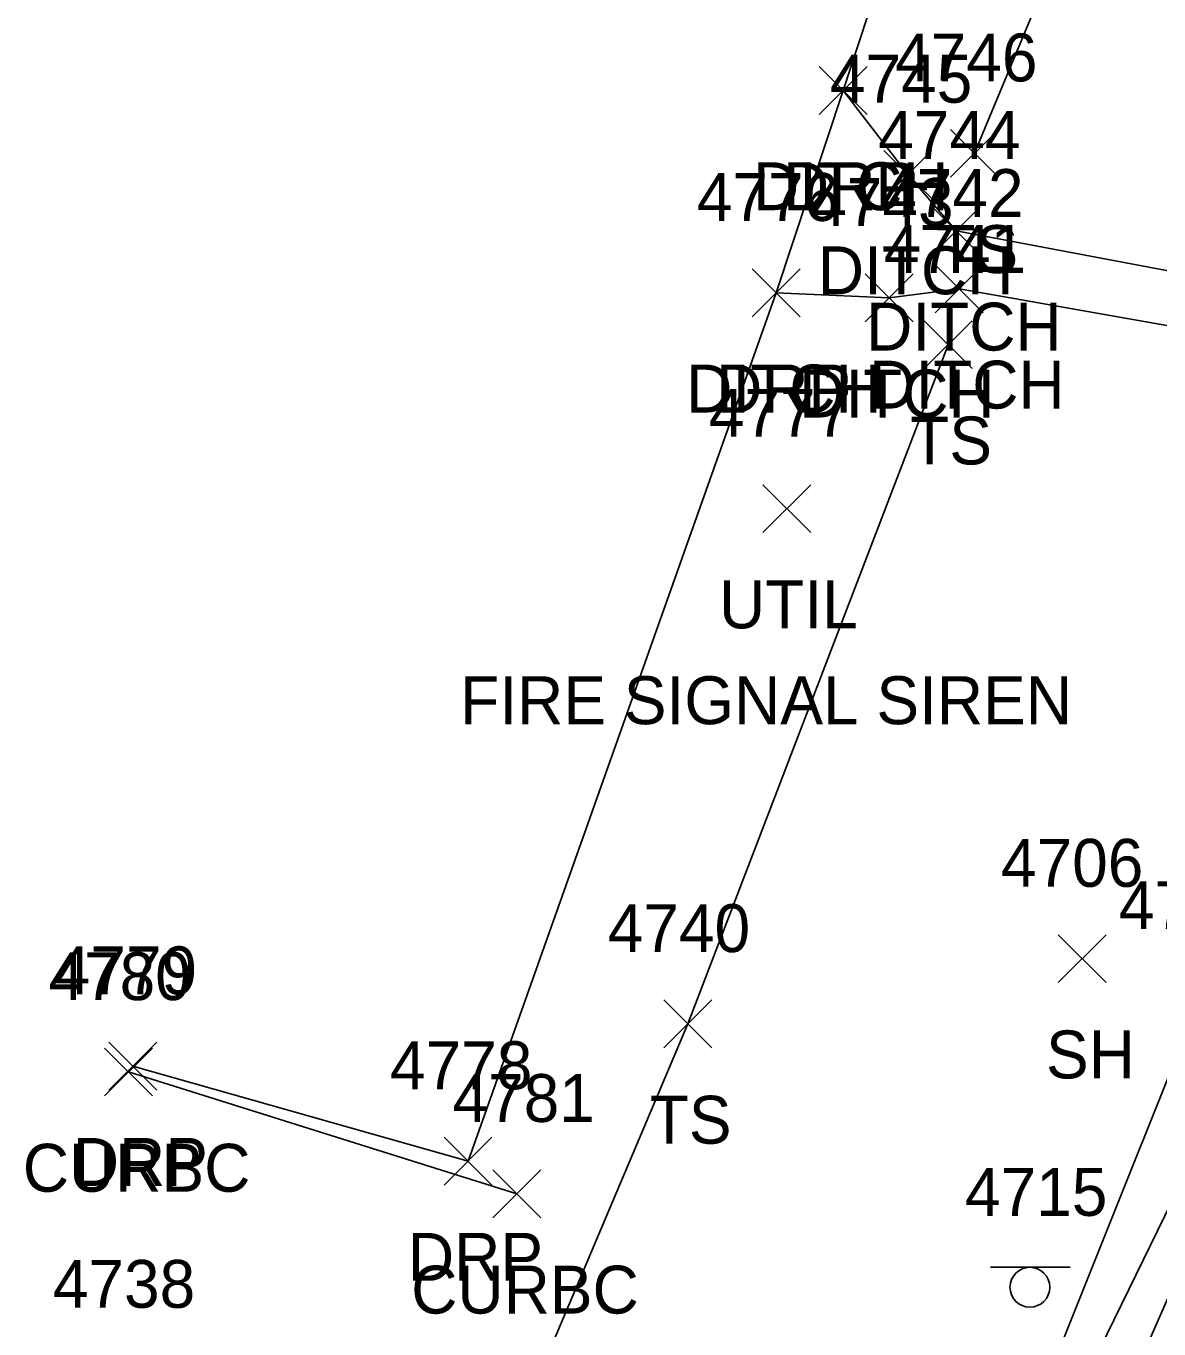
# Model space of a CAD drawing. Extents: x 1653135 to 1655489, y 602711 to 605684.
# Drawn here: x 1653501.9 to 1653549.3, y 604872.1 to 604926.5 of the extents above; entities that cross this region are included whole.
import ezdxf

# ---------------------------------------------------------------- set-up
doc = ezdxf.new("R2010")
doc.units = 0
for name, color, linetype in [('D_A', 7, 'Continuous'), ('D_I', 7, 'Continuous'), ('D_TIC', 7, 'Continuous'), ('DD', 7, 'Continuous'), ('L_A', 7, 'Continuous'), ('L_I', 7, 'Continuous'), ('L_TIC', 7, 'Continuous'), ('LELB', 7, 'Continuous'), ('R_A', 7, 'Continuous'), ('R_I', 7, 'Continuous'), ('R_TIC', 7, 'Continuous'), ('RC', 7, 'Continuous'), ('RDP', 7, 'Continuous'), ('S_I', 7, 'Continuous'), ('SSGN', 7, 'Continuous'), ('U_A', 7, 'Continuous'), ('U_C', 7, 'Continuous'), ('U_I', 7, 'Continuous'), ('UDEFAULT', 7, 'Continuous')]:
    doc.layers.add(name, color=color, linetype=linetype)

msp = doc.modelspace()

# ---------------------------------------------------------------- linework, layer by layer
at = {"layer": 'D_TIC'}
for points in [[(1653535.081, 604922.861), (1653537.081, 604924.861)], [(1653537.081, 604922.861), (1653535.081, 604924.861)], [(1653535.081, 604922.861), (1653537.081, 604924.861)], [(1653537.081, 604922.861), (1653535.081, 604924.861)], [(1653537.788, 604919.349), (1653539.788, 604921.349)], [(1653539.788, 604919.349), (1653537.788, 604921.349)], [(1653537.788, 604919.349), (1653539.788, 604921.349)], [(1653539.788, 604919.349), (1653537.788, 604921.349)], [(1653539.805, 604916.999), (1653541.805, 604918.999)], [(1653541.805, 604916.999), (1653539.805, 604918.999)], [(1653539.805, 604916.999), (1653541.805, 604918.999)], [(1653541.805, 604916.999), (1653539.805, 604918.999)], [(1653532.284, 604914.413), (1653534.284, 604916.413)], [(1653534.284, 604914.413), (1653532.284, 604916.413)], [(1653532.284, 604914.413), (1653534.284, 604916.413)], [(1653534.284, 604914.413), (1653532.284, 604916.413)], [(1653539.93, 604914.577), (1653541.93, 604916.577)], [(1653541.93, 604914.577), (1653539.93, 604916.577)], [(1653539.93, 604914.577), (1653541.93, 604916.577)], [(1653541.93, 604914.577), (1653539.93, 604916.577)], [(1653537.006, 604914.204), (1653539.006, 604916.204)], [(1653539.006, 604914.204), (1653537.006, 604916.204)], [(1653537.006, 604914.204), (1653539.006, 604916.204)], [(1653539.006, 604914.204), (1653537.006, 604916.204)]]:
    msp.add_lwpolyline(points, dxfattribs=at)
at = {"layer": 'DD'}
for points in [[(1653561.705, 604914.067), (1653540.805, 604917.999), (1653538.788, 604920.349), (1653536.081, 604923.861)], [(1653561.032, 604912.031), (1653540.93, 604915.577), (1653538.006, 604915.204), (1653533.284, 604915.413)]]:
    msp.add_lwpolyline(points, dxfattribs=at)
at = {"layer": 'L_TIC'}
for points in [[(1653540.566, 604920.237), (1653542.566, 604922.237)], [(1653542.566, 604920.237), (1653540.566, 604922.237)], [(1653540.566, 604920.237), (1653542.566, 604922.237)], [(1653542.566, 604920.237), (1653540.566, 604922.237)], [(1653539.474, 604912.245), (1653541.474, 604914.245)], [(1653541.474, 604912.245), (1653539.474, 604914.245)], [(1653539.474, 604912.245), (1653541.474, 604914.245)], [(1653541.474, 604912.245), (1653539.474, 604914.245)], [(1653545.068, 604886.609), (1653547.068, 604888.609)], [(1653547.068, 604886.609), (1653545.068, 604888.609)], [(1653545.068, 604886.609), (1653547.068, 604888.609)], [(1653547.068, 604886.609), (1653545.068, 604888.609)], [(1653528.593, 604883.883), (1653530.593, 604885.883)], [(1653530.593, 604883.883), (1653528.593, 604885.883)], [(1653528.593, 604883.883), (1653530.593, 604885.883)], [(1653530.593, 604883.883), (1653528.593, 604885.883)]]:
    msp.add_lwpolyline(points, dxfattribs=at)
at = {"layer": 'LELB'}
for points in [[(1653541.566, 604921.237), (1653548.903, 604938.867), (1653560.772, 604969.178), (1653570.052, 604991.652), (1653582.116, 605015.653), (1653593.342, 605040.174), (1653607.207, 605063.51), (1653620.438, 605089.521)], [(1653628.692, 605085.658), (1653616.928, 605051.253), (1653604.145, 605018.141), (1653588.98, 604978.643), (1653574.088, 604944.853), (1653561.705, 604914.067), (1653561.032, 604912.031), (1653550.936, 604885.841), (1653541.417, 604862.062)], [(1653631.596, 605085.072), (1653619.376, 605050.855), (1653605.785, 605017.644), (1653591.211, 604977.614), (1653577.689, 604945.476), (1653564.219, 604911.93), (1653553.433, 604884.868), (1653541.981, 604861.46), (1653536.551, 604855.109), (1653535.556, 604854.237)], [(1653632.967, 605084.757), (1653620.522, 605050.919), (1653607.73, 605017.428), (1653592.032, 604977.294), (1653579.847, 604945.831), (1653565.166, 604911.093), (1653554.426, 604884.303), (1653544.928, 604862.691)], [(1653506.324, 604870.029), (1653521.806, 604866.504), (1653529.593, 604884.883), (1653540.474, 604913.245)]]:
    msp.add_lwpolyline(points, dxfattribs=at)
at = {"layer": 'R_TIC'}
for points in [[(1653535.081, 604922.861), (1653537.081, 604924.861)], [(1653537.081, 604922.861), (1653535.081, 604924.861)], [(1653535.081, 604922.861), (1653537.081, 604924.861)], [(1653537.081, 604922.861), (1653535.081, 604924.861)], [(1653532.284, 604914.413), (1653534.284, 604916.413)], [(1653534.284, 604914.413), (1653532.284, 604916.413)], [(1653532.284, 604914.413), (1653534.284, 604916.413)], [(1653534.284, 604914.413), (1653532.284, 604916.413)], [(1653505.228, 604881.877), (1653507.228, 604883.877)], [(1653507.228, 604881.877), (1653505.228, 604883.877)], [(1653505.228, 604881.877), (1653507.228, 604883.877)], [(1653507.228, 604881.877), (1653505.228, 604883.877)], [(1653505.411, 604882.119), (1653507.411, 604884.119)], [(1653507.411, 604882.119), (1653505.411, 604884.119)], [(1653505.411, 604882.119), (1653507.411, 604884.119)], [(1653507.411, 604882.119), (1653505.411, 604884.119)], [(1653519.411, 604878.157), (1653521.411, 604880.157)], [(1653521.411, 604878.157), (1653519.411, 604880.157)], [(1653519.411, 604878.157), (1653521.411, 604880.157)], [(1653521.411, 604878.157), (1653519.411, 604880.157)], [(1653521.453, 604876.789), (1653523.453, 604878.789)], [(1653523.453, 604876.789), (1653521.453, 604878.789)], [(1653521.453, 604876.789), (1653523.453, 604878.789)], [(1653523.453, 604876.789), (1653521.453, 604878.789)]]:
    msp.add_lwpolyline(points, dxfattribs=at)
at = {"layer": 'RC'}
msp.add_lwpolyline([(1653506.228, 604882.877), (1653522.453, 604877.789)], dxfattribs=at)
at = {"layer": 'RDP'}
msp.add_lwpolyline([(1653543.593, 604970.748), (1653546.598, 604962.327), (1653544.89, 604950.623), (1653536.081, 604923.861), (1653533.284, 604915.413), (1653520.411, 604879.157), (1653506.411, 604883.119)], dxfattribs=at)
at = {"layer": 'SSGN'}
for p, q in [((1653542.237, 604874.723), (1653545.571, 604874.723)), ((1653543.884, 604873.889), (1653543.884, 604873.889))]:
    msp.add_line(p, q, dxfattribs=at)
msp.add_circle((1653543.884, 604873.889), 0.833, dxfattribs=at)
at = {"layer": 'UDEFAULT'}
for points in [[(1653532.729, 604905.399), (1653534.729, 604907.399)], [(1653534.729, 604905.399), (1653532.729, 604907.399)]]:
    msp.add_lwpolyline(points, dxfattribs=at)

# ---------------------------------------------------------------- texts
at = {"layer": 'D_A'}
for p in [(1653532.317, 604918.861), (1653532.317, 604918.861), (1653535.024, 604915.349), (1653535.024, 604915.349), (1653537.041, 604912.999), (1653537.041, 604912.999), (1653529.521, 604910.413), (1653529.521, 604910.413), (1653537.167, 604910.577), (1653537.167, 604910.577), (1653534.242, 604910.204), (1653534.242, 604910.204)]:
    msp.add_text('DITCH', height=2, dxfattribs=at).set_placement(p)
at = {"layer": 'D_I'}
for s, p in [('4745', (1653535.528, 604923.349)), ('4745', (1653535.528, 604923.349)), ('4744', (1653537.545, 604920.999)), ('4744', (1653537.545, 604920.999)), ('4742', (1653537.671, 604918.577)), ('4742', (1653537.671, 604918.577)), ('4776', (1653529.969, 604918.413)), ('4776', (1653529.969, 604918.413)), ('4743', (1653534.746, 604918.204)), ('4743', (1653534.746, 604918.204))]:
    msp.add_text(s, height=2, dxfattribs=at).set_placement(p)
at = {"layer": 'L_A'}
for s, p in [('TS', (1653539.976, 604916.237)), ('TS', (1653539.976, 604916.237)), ('TS', (1653538.883, 604908.245)), ('TS', (1653538.883, 604908.245)), ('SH', (1653544.557, 604882.609)), ('SH', (1653544.557, 604882.609)), ('TS', (1653528.002, 604879.883)), ('TS', (1653528.002, 604879.883))]:
    msp.add_text(s, height=2, dxfattribs=at).set_placement(p)
at = {"layer": 'L_I'}
for s, p in [('4746', (1653538.252, 604924.237)), ('4746', (1653538.252, 604924.237)), ('4741', (1653537.781, 604916.245)), ('4741', (1653537.781, 604916.245)), ('4706', (1653542.675, 604890.609)), ('4706', (1653542.675, 604890.609)), ('4707', (1653547.598, 604888.841)), ('4707', (1653547.598, 604888.841)), ('4740', (1653526.247, 604887.883)), ('4740', (1653526.247, 604887.883)), ('4738', (1653503.064, 604873.029)), ('4738', (1653503.064, 604873.029))]:
    msp.add_text(s, height=2, dxfattribs=at).set_placement(p)
at = {"layer": 'R_A'}
for s, p in [('DRP', (1653533.569, 604918.861)), ('DRP', (1653533.569, 604918.861)), ('DRP', (1653530.772, 604910.413)), ('DRP', (1653530.772, 604910.413)), ('CURBC', (1653501.81, 604877.877)), ('CURBC', (1653501.81, 604877.877)), ('DRP', (1653503.899, 604878.119)), ('DRP', (1653503.899, 604878.119)), ('DRP', (1653517.899, 604874.157)), ('DRP', (1653517.899, 604874.157)), ('CURBC', (1653518.036, 604872.789)), ('CURBC', (1653518.036, 604872.789))]:
    msp.add_text(s, height=2, dxfattribs=at).set_placement(p)
at = {"layer": 'R_I'}
for s, p in [('4776', (1653529.969, 604918.413)), ('4776', (1653529.969, 604918.413)), ('4779', (1653503.144, 604886.119)), ('4779', (1653503.144, 604886.119)), ('4780', (1653502.881, 604885.877)), ('4780', (1653502.881, 604885.877)), ('4778', (1653517.151, 604882.157)), ('4778', (1653517.151, 604882.157)), ('4781', (1653519.761, 604880.789)), ('4781', (1653519.761, 604880.789))]:
    msp.add_text(s, height=2, dxfattribs=at).set_placement(p)
at = {"layer": 'S_I'}
msp.add_text('4715', height=2, dxfattribs=at).set_placement((1653541.172, 604876.869))
at = {"layer": 'U_A'}
msp.add_text('UTIL', height=2, dxfattribs=at).set_placement((1653530.894, 604901.399))
at = {"layer": 'U_C'}
msp.add_text('FIRE SIGNAL SIREN', height=2, dxfattribs=at).set_placement((1653520.084, 604897.399))
at = {"layer": 'U_I'}
msp.add_text('4777', height=2, dxfattribs=at).set_placement((1653530.469, 604909.399))

doc.saveas('drawing.dxf')
